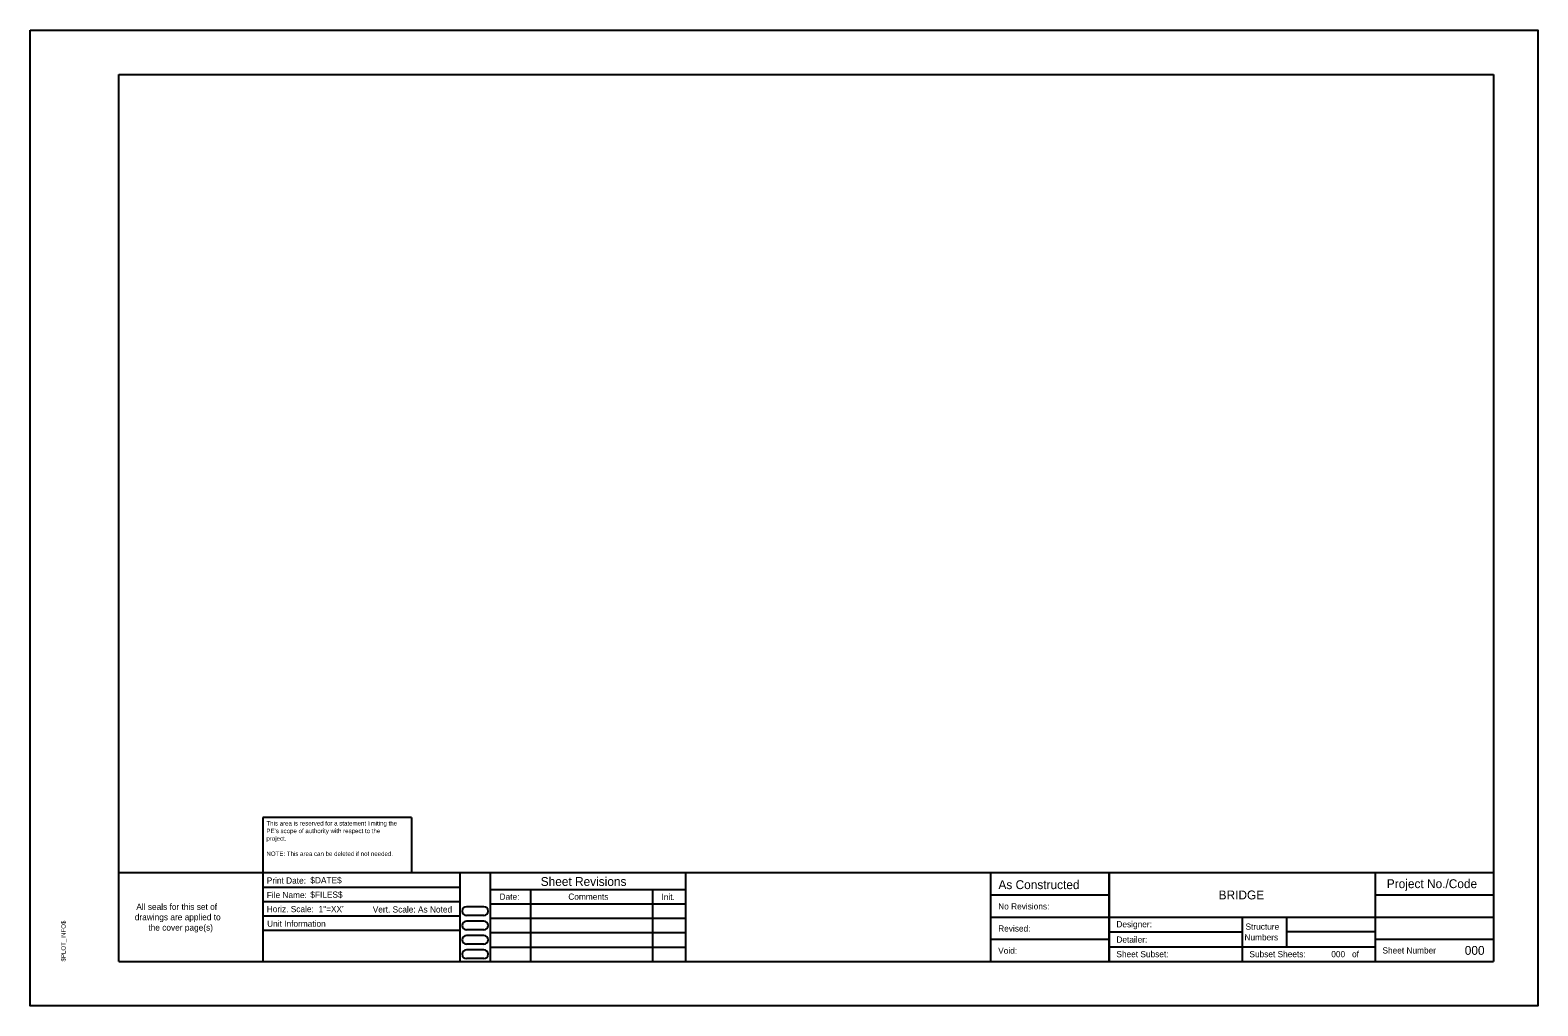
# Model space of a CAD drawing. Extents: x 0 to 17, y 0 to 11.
import ezdxf

# ---------------------------------------------------------------- set-up
doc = ezdxf.new("R2010")
doc.units = 0
for name, color, linetype in [('DRAFT_Information-No Plot', 7, 'Continuous'), ('SHEET_Lines', 7, 'Continuous'), ('SHEET_Plot Boundary', 7, 'Continuous'), ('SHEET_Text-Border Info', 7, 'Continuous'), ('SHEET_Text-Sheet Number', 7, 'Continuous'), ('SHEET_Text-Titles', 7, 'Continuous')]:
    doc.layers.add(name, color=color, linetype=linetype)

msp = doc.modelspace()

# ---------------------------------------------------------------- linework, layer by layer
at = {"layer": 'DRAFT_Information-No Plot'}
for p, q in [((4.3, 2.125), (2.625, 2.125)), ((2.625, 2.125), (2.625, 1.5)), ((4.3, 2.125), (4.3, 1.5)), ((1, 0.5), (1, 0.5))]:
    msp.add_line(p, q, dxfattribs=at)
at = {"layer": 'SHEET_Lines'}
for p, q in [((1, 10.5), (16.5, 10.5)), ((1, 0.5), (1, 10.5)), ((16.5, 10.5), (16.5, 0.5)), ((16.5, 1.5), (1, 1.5)), ((2.625, 1.5), (2.625, 0.5)), ((4.85, 0.5), (4.85, 1.5)), ((5.189, 0.5), (5.189, 1.5)), ((7.392, 0.5), (7.392, 1.5)), ((10.833, 0.5), (10.833, 1.5)), ((12.167, 1.5), (12.167, 0.5)), ((12.167, 0.5), (12.167, 1.5)), ((15.167, 1.5), (15.167, 0.5)), ((2.625, 1.338), (4.85, 1.338)), ((5.189, 1.313), (7.392, 1.313)), ((5.647, 0.5), (5.647, 1.313)), ((7.022, 0.5), (7.022, 1.313)), ((10.833, 1.25), (12.167, 1.25)), ((15.167, 1.25), (16.5, 1.25)), ((2.625, 1.175), (4.85, 1.175)), ((5.116, 1.118), (4.92, 1.118)), ((5.189, 1.15), (7.392, 1.15)), ((2.625, 1.013), (4.85, 1.013)), ((4.85, 0.85), (2.625, 0.85)), ((5.116, 1.02), (4.92, 1.02)), ((5.116, 0.955), (4.92, 0.955)), ((5.116, 0.857), (4.92, 0.857)), ((5.189, 0.988), (7.392, 0.988)), ((10.833, 1), (16.5, 1)), ((13.667, 1), (13.667, 0.5)), ((14.167, 1), (14.167, 0.667)), ((5.116, 0.793), (4.92, 0.793)), ((5.116, 0.695), (4.92, 0.695)), ((5.189, 0.825), (7.392, 0.825)), ((10.833, 0.75), (12.167, 0.75)), ((12.167, 0.833), (13.667, 0.833)), ((15.167, 0.833), (14.167, 0.833)), ((15.167, 0.75), (16.5, 0.75)), ((5.116, 0.63), (4.92, 0.63)), ((5.116, 0.532), (4.92, 0.532)), ((5.189, 0.663), (7.392, 0.663)), ((12.167, 0.667), (15.167, 0.667)), ((1, 0.5), (16.5, 0.5))]:
    msp.add_line(p, q, dxfattribs=at)
for centre, start, end in [((4.92, 1.069), 90, 270), ((5.116, 1.069), 270, 90), ((4.92, 0.906), 90, 270), ((5.116, 0.906), 270, 90), ((4.92, 0.744), 90, 270), ((5.116, 0.744), 270, 90), ((4.92, 0.581), 90, 270), ((5.116, 0.581), 270, 90)]:
    msp.add_arc(centre, 0.0491, start, end, dxfattribs=at)
at = {"layer": 'SHEET_Plot Boundary'}
msp.add_lwpolyline([(0, 11), (17, 11), (17, 0), (0, 0)], close=True, dxfattribs=at)

# ---------------------------------------------------------------- texts
at = {"layer": 'DRAFT_Information-No Plot'}
for s, p in [('This area is reserved for a statement limiting the', (2.664, 2.033)), ('project.', (2.664, 1.862)), ("PE's scope of authority with respect to the ", (2.664, 1.947)), ('NOTE: This area can be deleted if not needed.', (2.664, 1.69))]:
    msp.add_text(s, height=0.05, dxfattribs=at).set_placement(p)
at = {"layer": 'SHEET_Text-Border Info'}
for s, p in [('Print Date:', (2.668, 1.378)), ('$DATE$', (3.159, 1.381)), ('File Name:', (2.668, 1.215)), ('$FILES$', (3.159, 1.219)), ('Date:', (5.293, 1.196)), ('Comments', (6.068, 1.196)), ('Init.', (7.119, 1.193)), ('drawings are applied to', (1.18, 0.965)), ('All seals for this set of', (1.197, 1.082)), ('Horiz. Scale:', (2.668, 1.056)), ('1"=XX\'', (3.252, 1.056)), ('Vert. Scale: As Noted', (3.863, 1.052)), ('No Revisions:', (10.915, 1.087)), ('the cover page(s)', (1.333, 0.848)), ('Unit Information', (2.672, 0.892)), ('Revised:', (10.915, 0.837)), ('Designer:', (12.248, 0.885)), ('Structure', (13.704, 0.858)), ('Detailer:', (12.248, 0.712)), ('Numbers', (13.692, 0.738)), ('Void:', (10.915, 0.587)), ('Sheet Subset:', (12.248, 0.548)), ('Subset Sheets:', (13.748, 0.548)), ('000', (14.671, 0.548)), (' of ', (14.879, 0.548)), ('Sheet Number', (15.248, 0.59))]:
    msp.add_text(s, height=0.07, dxfattribs=at).set_placement(p)
msp.add_text('$PLOT_INFO$', height=0.05, rotation=90, dxfattribs=at).set_placement((0.4, 0.5))
at = {"layer": 'SHEET_Text-Sheet Number'}
msp.add_text('000', height=0.1, dxfattribs=at).set_placement((16.176, 0.575))
at = {"layer": 'SHEET_Text-Titles'}
for s, p in [('Sheet Revisions', (5.757, 1.352)), ('As Constructed', (10.918, 1.316)), ('Project No./Code', (15.297, 1.327)), ('BRIDGE', (13.401, 1.2))]:
    msp.add_text(s, height=0.1, dxfattribs=at).set_placement(p)

doc.saveas('drawing.dxf')
